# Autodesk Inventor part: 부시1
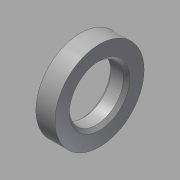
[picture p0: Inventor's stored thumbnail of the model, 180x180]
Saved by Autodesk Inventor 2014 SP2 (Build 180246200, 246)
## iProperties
Created: 2015-09
Part Number: 부시1
Material: 강철, 연강
Document SubType Name: Modeling
Designer: mduedu
Density: 7.86 g/cm^3
Description: 외주 가공
Mass: 17.8983 g
Surface Area: 15.6581 cm^2
Volume: 2.27713 cm^3
Appearance: 강철
Author: mduedu
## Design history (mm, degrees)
sketch "스케치1"
  geometry: C1 r 14 at (0, 0); C2 r 8.5 at (0, 0); 1 further point
  constraints: 2 centre point, 2 coincident
  dimensions: "d0" = 28 diameter of C1; "d2" = 17 diameter of C2
extrude "돌출1" new body sketch "스케치1" distance "d3" = 6; taper "d4" = 0 deg
chamfer "모따기1" distance "d5" = 1; stored, may be unused: second distance "d6" = 2, angle "d7" = 45 deg
node "솔리드1"
